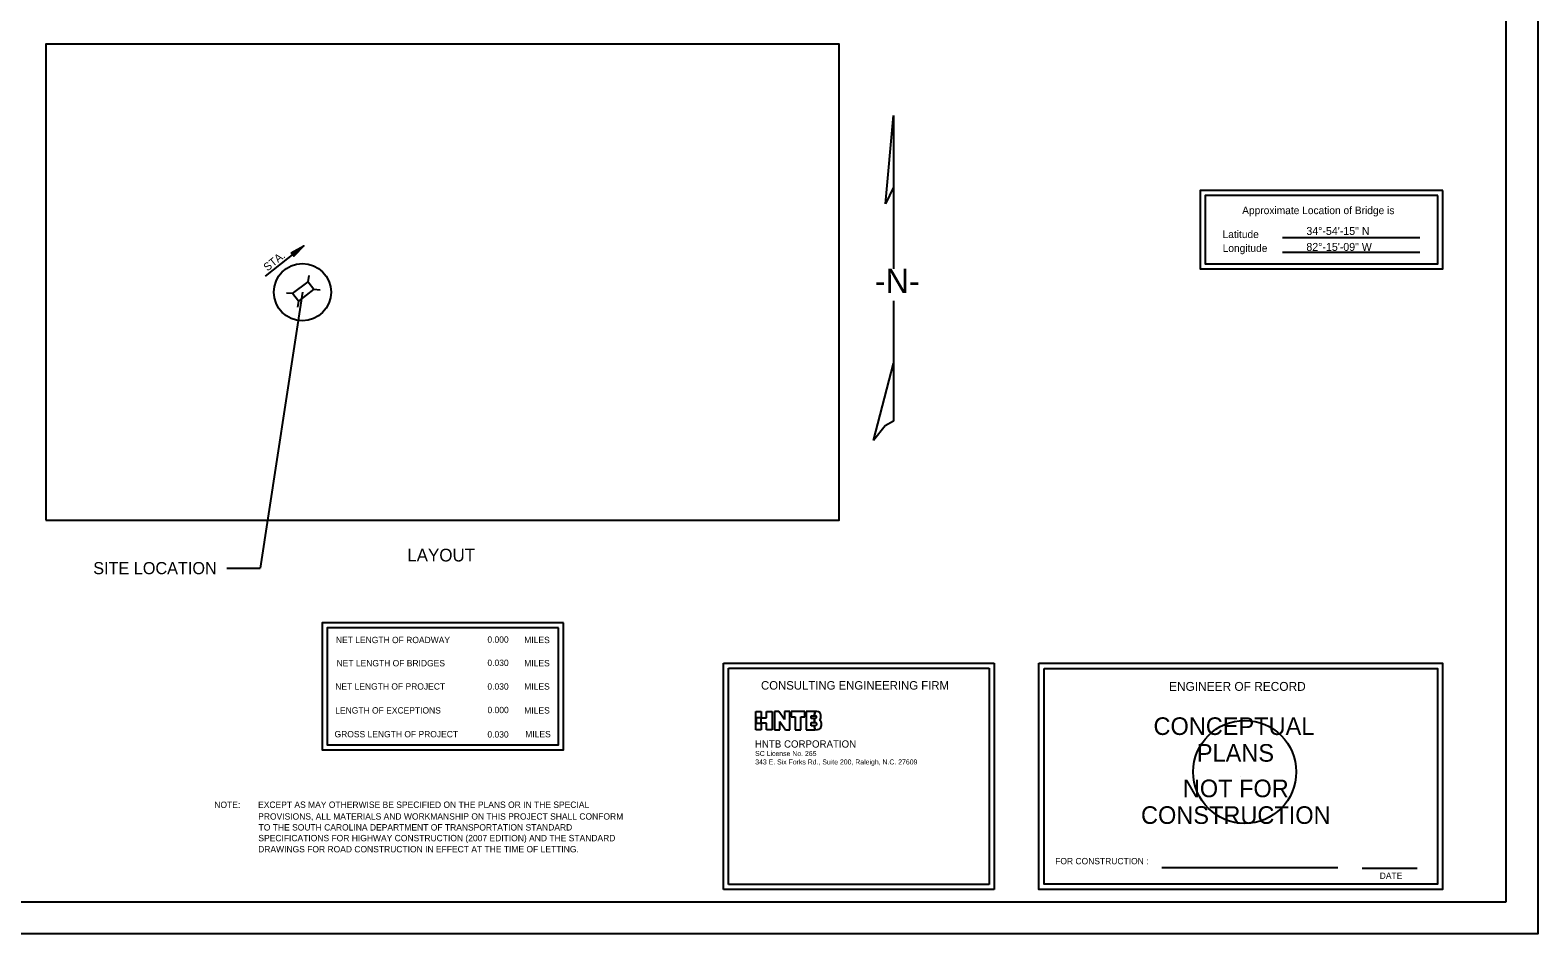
# Model space of a CAD drawing. Extents: x 0 to 4.05, y -2.5 to 2.32.
# Drawn here: x 1.021 to 3, y -2.5 to -1.314 of the extents above; entities that cross this region are included whole.
import ezdxf

# ---------------------------------------------------------------- set-up
doc = ezdxf.new("R2010")
doc.units = 0
for name, color, linetype in [('BR_AUTO DIMENSION', 7, 'Continuous'), ('BR_BORDER LINES', 7, 'Continuous'), ('BR_DETAILS', 7, 'Continuous'), ('BR_TEXT', 7, 'Continuous'), ('Default', 7, 'Continuous'), ('NoPlot', 7, 'Continuous'), ('V7_23', 7, 'Continuous')]:
    doc.layers.add(name, color=color, linetype=linetype)

msp = doc.modelspace()

# ---------------------------------------------------------------- linework, layer by layer
at = {"layer": 'BR_AUTO DIMENSION'}
for p, q in [((2.1436, -1.5418), (2.1542, -1.4259)), ((2.1542, -1.4259), (2.1542, -1.5203)), ((2.1542, -1.5203), (2.1436, -1.5418)), ((2.1542, -1.5203), (2.1542, -1.5857)), ((2.1542, -1.5857), (2.1542, -1.6274)), ((1.378, -1.6579), (1.3227, -2.02)), ((2.1542, -1.6691), (2.1542, -1.7516)), ((2.1279, -1.8526), (2.1542, -1.7516)), ((2.1542, -1.7516), (2.1542, -1.7641)), ((2.1542, -1.7641), (2.1542, -1.8273)), ((1.2789, -2.02), (1.3227, -2.02)), ((1.931, -2.1449), (2.286, -2.1449)), ((1.931, -2.4416), (1.931, -2.1449)), ((1.9373, -2.1513), (2.2796, -2.1513)), ((1.9373, -2.4352), (1.9373, -2.1513)), ((2.2796, -2.1513), (2.2796, -2.4352)), ((2.286, -2.1449), (2.286, -2.4416)), ((2.286, -2.4416), (1.931, -2.4416)), ((2.2796, -2.4352), (1.9373, -2.4352))]:
    msp.add_line(p, q, dxfattribs=at)
msp.add_lwpolyline([(2.1542, -1.8273), (2.1429, -1.8334), (2.1279, -1.8526)], dxfattribs=at)
msp.add_circle((1.378, -1.6579), 0.0376, dxfattribs=at)
at = {"layer": 'BR_BORDER LINES'}
for p, q in [((2.9583, -2.4582), (2.9583, -0.7082)), ((2.9583, -1.3928), (2.9583, -0.8053)), ((0.1667, -2.4582), (2.9583, -2.4582))]:
    msp.add_line(p, q, dxfattribs=at)
msp.add_lwpolyline([(1.0411, -1.9573), (2.0828, -1.9573), (2.0828, -1.3323), (1.0411, -1.3323)], close=True, dxfattribs=at)
at = {"layer": 'BR_DETAILS'}
for p, q in [((2.6649, -1.5862), (2.8452, -1.5862)), ((2.6649, -1.6056), (2.8452, -1.6056)), ((2.5063, -2.4129), (2.7373, -2.4129)), ((2.7692, -2.4138), (2.8416, -2.4138))]:
    msp.add_line(p, q, dxfattribs=at)
for points in [[(2.8752, -1.5246), (2.5568, -1.5246), (2.5568, -1.6272), (2.8752, -1.6272)], [(2.8685, -1.5312), (2.5634, -1.5312), (2.5634, -1.6206), (2.8685, -1.6206)], [(2.345, -2.1449), (2.875, -2.1449), (2.875, -2.4416), (2.345, -2.4416)], [(2.3517, -2.1516), (2.8683, -2.1516), (2.8683, -2.4349), (2.3517, -2.4349)]]:
    msp.add_lwpolyline(points, close=True, dxfattribs=at)
at = {"layer": 'BR_TEXT'}
for p, q in [((1.3296, -1.637), (1.3797, -1.5969)), ((1.3855, -1.6442), (1.3868, -1.6362)), ((1.3652, -1.6598), (1.3571, -1.659)), ((1.393, -1.654), (1.4011, -1.6549)), ((1.3727, -1.6696), (1.3715, -1.6776))]:
    msp.add_line(p, q, dxfattribs=at)
for points in [[(1.3634, -1.6064), (1.3797, -1.5969), (1.3669, -1.6107)], [(1.3855, -1.6442), (1.393, -1.654), (1.3727, -1.6696), (1.3652, -1.6598)], [(1.7207, -2.0919), (1.4041, -2.0919), (1.4041, -2.2586), (1.7207, -2.2586)], [(1.7141, -2.0986), (1.4107, -2.0986), (1.4107, -2.2519), (1.7141, -2.2519)]]:
    msp.add_lwpolyline(points, close=True, dxfattribs=at)
at = {"layer": 'Default'}
msp.add_line((2.61, -2.2932), (2.61, -2.2932), dxfattribs=at)
at = {"layer": 'NoPlot'}
msp.add_lwpolyline([(0, -0.6667), (3, -0.6667), (3, -2.5), (0, -2.5)], close=True, dxfattribs=at)
msp.add_circle((2.6152, -2.2875), 0.0676, dxfattribs=at)
at = {"layer": 'V7_23'}
for p, q in [((1.9733, -2.2323), (1.9733, -2.2083)), ((1.9733, -2.2083), (1.9804, -2.2083)), ((1.9804, -2.2164), (1.9736, -2.2164)), ((1.9736, -2.2164), (1.9736, -2.2235)), ((1.9804, -2.2083), (1.9804, -2.2164)), ((1.9804, -2.2235), (1.9804, -2.2164)), ((1.9804, -2.2164), (1.9875, -2.2164)), ((1.9875, -2.2164), (1.9875, -2.2083)), ((1.9875, -2.2083), (1.9946, -2.2083)), ((1.9946, -2.2083), (1.9946, -2.2323)), ((2.0037, -2.2083), (1.9978, -2.2083)), ((1.9978, -2.2083), (1.9978, -2.2323)), ((2.0108, -2.2188), (2.0037, -2.2083)), ((2.0178, -2.2083), (2.0108, -2.2083)), ((2.0108, -2.2083), (2.0108, -2.2188)), ((2.0178, -2.2323), (2.0178, -2.2083)), ((2.0198, -2.2083), (2.0198, -2.2153)), ((2.0375, -2.2083), (2.0198, -2.2083)), ((2.0198, -2.2153), (2.0251, -2.2153)), ((2.0251, -2.2153), (2.0251, -2.2323)), ((2.0322, -2.2323), (2.0322, -2.2153)), ((2.0322, -2.2153), (2.0375, -2.2153)), ((2.0375, -2.2153), (2.0375, -2.2083)), ((2.0507, -2.2083), (2.0396, -2.2083)), ((2.0396, -2.2083), (2.0396, -2.2323)), ((2.0461, -2.2172), (2.0461, -2.2137)), ((2.0461, -2.2137), (2.0503, -2.2137)), ((2.0503, -2.2137), (2.0507, -2.2083)), ((2.0507, -2.2083), (2.0503, -2.2137)), ((1.9804, -2.2323), (1.9733, -2.2323)), ((1.9736, -2.2235), (1.9804, -2.2235)), ((1.9875, -2.2235), (1.9804, -2.2235)), ((1.9804, -2.2235), (1.9804, -2.2323)), ((1.9875, -2.2323), (1.9875, -2.2235)), ((1.9946, -2.2323), (1.9875, -2.2323)), ((1.9978, -2.2323), (2.0048, -2.2323)), ((2.0048, -2.2323), (2.0048, -2.2215)), ((2.0048, -2.2215), (2.0121, -2.2323)), ((2.0121, -2.2323), (2.0178, -2.2323)), ((2.0251, -2.2323), (2.0322, -2.2323)), ((2.0396, -2.2323), (2.0506, -2.2323)), ((2.0505, -2.2172), (2.0461, -2.2172)), ((2.0461, -2.227), (2.0461, -2.2225)), ((2.0461, -2.2225), (2.0502, -2.2225)), ((2.0503, -2.227), (2.0461, -2.227)), ((2.0502, -2.2225), (2.0505, -2.2172)), ((2.0505, -2.2172), (2.0502, -2.2225)), ((2.0506, -2.2323), (2.0503, -2.227)), ((2.0503, -2.227), (2.0506, -2.2323))]:
    msp.add_line(p, q, dxfattribs=at)
for points in [[(2.0503, -2.2137), (2.0522, -2.2137), (2.0524, -2.2149), (2.0524, -2.2155), (2.0524, -2.2161), (2.052, -2.2172), (2.0505, -2.2172)], [(2.0568, -2.2194), (2.0582, -2.2182), (2.0588, -2.2165), (2.0588, -2.2153), (2.0588, -2.211), (2.0557, -2.2083), (2.0507, -2.2083), (2.0507, -2.2083), (2.0507, -2.2083), (2.0506, -2.2083)], [(2.0502, -2.2225), (2.0524, -2.2225), (2.0528, -2.2237), (2.0528, -2.2247), (2.0528, -2.2261), (2.0519, -2.227), (2.0503, -2.227)], [(2.0506, -2.2323), (2.0561, -2.2323), (2.0595, -2.2292), (2.0595, -2.2242), (2.0595, -2.2223), (2.0585, -2.2205), (2.0568, -2.2194)]]:
    msp.add_open_spline(points, degree=3, dxfattribs=at)

# ---------------------------------------------------------------- texts
at = {"layer": 'BR_AUTO DIMENSION'}
for s, p in [('34°-54\'-15" N', (2.6961, -1.5828)), ('82°-15\'-09" W', (2.6961, -1.6037))]:
    msp.add_text(s, height=0.010417, dxfattribs=at).set_placement(p)
msp.add_text('-N-', height=0.03184, rotation=360, dxfattribs=at).set_placement((2.1294, -1.6591))
at = {"layer": 'BR_DETAILS'}
for s, height, p in [('Approximate Location of Bridge is', 0.01, (2.6118, -1.5555)), ('Latitude', 0.01, (2.5861, -1.5869)), ('Longitude', 0.01, (2.5862, -1.6051)), ('LAYOUT', 0.01667, (1.5156, -2.0113)), ('ENGINEER OF RECORD', 0.011667, (2.5158, -2.1811)), ('NOTE:', 0.00833, (1.2624, -2.3348)), ('EXCEPT AS MAY OTHERWISE BE SPECIFIED ON THE PLANS OR IN THE SPECIAL ', 0.008334, (1.3198, -2.3347)), ('PROVISIONS, ALL MATERIALS AND WORKMANSHIP ON THIS PROJECT SHALL CONFORM ', 0.008334, (1.3199, -2.3501)), ('TO THE SOUTH CAROLINA DEPARTMENT OF TRANSPORTATION STANDARD ', 0.008334, (1.3205, -2.3644)), ('SPECIFICATIONS FOR HIGHWAY CONSTRUCTION (2007 EDITION) AND THE STANDARD', 0.008334, (1.3202, -2.3785)), ('DRAWINGS FOR ROAD CONSTRUCTION IN EFFECT AT THE TIME OF LETTING.', 0.008334, (1.3199, -2.3931)), ('FOR CONSTRUCTION :', 0.008333, (2.3663, -2.4087)), ('DATE', 0.00833, (2.7924, -2.4279))]:
    msp.add_text(s, height=height, dxfattribs=at).set_placement(p)
for s, height, p in [('CONCEPTUAL', 0.02311, (2.4954, -2.239)), ('PLANS', 0.02311, (2.5523, -2.2741)), ('NOT FOR', 0.02311, (2.5339, -2.3207)), ('CONSTRUCTION', 0.023108, (2.479, -2.3557))]:
    msp.add_text(s, height=height, rotation=360, dxfattribs=at).set_placement(p)
at = {"layer": 'BR_TEXT'}
for s, height, rotation, p in [('STA.', 0.01042, 38.6976, (1.3321, -1.6309)), ('SITE LOCATION ', 0.015922, 360, (1.1034, -2.028)), ('CONSULTING ENGINEERING FIRM', 0.011145, 0, (1.9801, -2.1795))]:
    msp.add_text(s, height=height, rotation=rotation, dxfattribs=at).set_placement(p)
for s, height, p in [('NET LENGTH OF ROADWAY', 0.008333, (1.422, -2.1185)), ('0.000', 0.00833, (1.6209, -2.118)), ('MILES', 0.00833, (1.6693, -2.1185)), ('NET LENGTH OF BRIDGES', 0.008333, (1.4228, -2.149)), ('0.030', 0.00833, (1.6209, -2.1485)), ('MILES', 0.00833, (1.6693, -2.149)), ('NET LENGTH OF PROJECT', 0.008333, (1.4211, -2.1795)), ('0.030', 0.00833, (1.6209, -2.1796)), ('MILES', 0.00833, (1.6693, -2.1795)), ('LENGTH OF EXCEPTIONS', 0.008333, (1.4211, -2.2109)), ('0.000', 0.00833, (1.621, -2.2104)), ('MILES', 0.00833, (1.6693, -2.2109)), ('GROSS LENGTH OF PROJECT', 0.008333, (1.4202, -2.2421)), ('0.030', 0.00833, (1.6209, -2.2424)), ('MILES', 0.00833, (1.6706, -2.2421)), ('HNTB CORPORATION', 0.009516, (1.9721, -2.2556)), ('SC License No. 265', 0.006558, (1.9724, -2.2666)), ('343 E. Six Forks Rd., Suite 200, Raleigh, N.C. 27609', 0.006558, (1.9725, -2.2777))]:
    msp.add_text(s, height=height, dxfattribs=at).set_placement(p)

doc.saveas('drawing.dxf')
